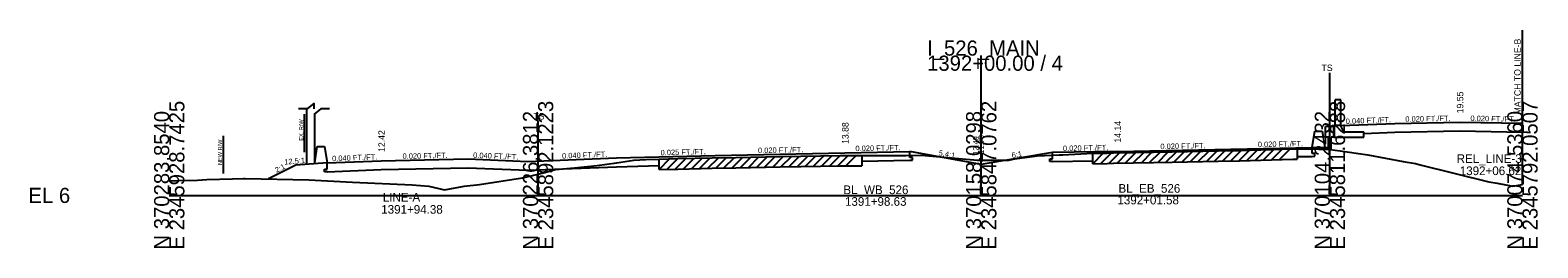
# Model space of a CAD drawing. Extents: x -170 to 2527928, y -10 to 1619750.
# Drawn here: x 1974.3 to 2252.8, y 4990.3 to 5030.5 of the extents above; entities that cross this region are included whole.
import ezdxf

# ---------------------------------------------------------------- set-up
doc = ezdxf.new("R2010")
doc.units = 0
for name, color, linetype in [('Default', 7, 'Continuous'), ('RD_GPK_XS_Cell', 7, 'Continuous'), ('RD_PD_NOISE-WALL-GM', 7, 'Continuous'), ('RD_PD_WallFill', 7, 'Continuous'), ('RD_XS_Base', 7, 'Continuous'), ('RD_XS_EarthShd', 7, 'Continuous'), ('RD_XS_ExGround', 7, 'Continuous'), ('RD_XS_ExPaveRet', 7, 'Continuous'), ('RD_XS_ExRW', 7, 'Continuous'), ('RD_XS_MatchLine', 7, 'Continuous'), ('RD_XS_NewRW', 7, 'Continuous'), ('RD_XS_Pave', 7, 'Continuous'), ('RD_XS_PaveShd', 7, 'Continuous'), ('RD_XS_TieSlope', 7, 'Continuous'), ('RD_XS_TX_Elev_EX', 7, 'Continuous'), ('RD_XS_TX_Elev_PR', 7, 'Continuous'), ('RD_XS_TX_Slope', 7, 'Continuous'), ('RD_XS_TX_Station', 7, 'Continuous')]:
    doc.layers.add(name, color=color, linetype=linetype)

msp = doc.modelspace()

# ---------------------------------------------------------------- linework, layer by layer
at = {"layer": 'Default'}
for p, q in [((2026.75, 5017.06), (2025.5, 5016.03)), ((2026.75, 5016.03), (2026.75, 5017.06)), ((2025.5, 5016.03), (2023.91, 5016.03)), ((2028, 5016.03), (2026.75, 5015.01)), ((2029.59, 5016.03), (2028, 5016.03))]:
    msp.add_line(p, q, dxfattribs=at)
at = {"layer": 'RD_GPK_XS_Cell'}
for p, q in [((2150.01, 5000), (2150.01, 5025.83)), ((2000, 5000), (2068.15, 5000)), ((2068.15, 5000), (2150.01, 5000)), ((2150.01, 5000), (2214.42, 5000)), ((2214.42, 5000), (2250, 5000))]:
    msp.add_line(p, q, dxfattribs=at)
at = {"layer": 'RD_PD_NOISE-WALL-GM'}
for p, q in [((2025.37, 5016.03), (2025.37, 5005.71)), ((2026.87, 5005.83), (2026.87, 5015.11)), ((2211.17, 5008.86), (2211.66, 5011.86)), ((2211.66, 5011.86), (2213, 5011.86)), ((2213, 5011.86), (2213.48, 5008.86)), ((2026.87, 5006.02), (2027.35, 5009.02)), ((2027.35, 5009.02), (2028.69, 5009.02)), ((2028.69, 5009.02), (2029.17, 5006.02))]:
    msp.add_line(p, q, dxfattribs=at)
at = {"layer": 'RD_PD_WallFill'}
for p, q in [((2215.42, 5012.91), (2215.42, 5017.66)), ((2216.42, 5017.66), (2215.42, 5017.66)), ((2216.42, 5012.91), (2216.42, 5017.66)), ((2215.14, 5012.74), (2213.64, 5012.74)), ((2213.64, 5010.74), (2213.64, 5012.74)), ((2215.3, 5012.91), (2215.13, 5012.74)), ((2215.14, 5010.74), (2215.14, 5012.74)), ((2215.21, 5012.74), (2215.14, 5012.74)), ((2215.21, 5012.82), (2215.21, 5010.74)), ((2216.42, 5012.91), (2215.3, 5012.91)), ((2216.42, 5012.91), (2216.42, 5012.74)), ((2216.42, 5012.74), (2216.92, 5011.74)), ((2216.92, 5011.74), (2220.71, 5011.74)), ((2220.71, 5010.74), (2220.71, 5011.74)), ((2214.14, 5010.74), (2213.64, 5010.74)), ((2214.14, 5008.51), (2214.14, 5010.74)), ((2215.14, 5010.74), (2214.64, 5010.74)), ((2214.64, 5008.47), (2214.64, 5010.74)), ((2215.14, 5010.74), (2220.71, 5010.74)), ((2215.21, 5010.74), (2215.14, 5010.74))]:
    msp.add_line(p, q, dxfattribs=at)
at = {"layer": 'RD_XS_Base'}
for p, q in [((2220.71, 5011.44), (2226.42, 5011.67)), ((2226.42, 5011.67), (2238.42, 5011.91)), ((2238.42, 5011.91), (2250, 5011.68)), ((2136.84, 5006.99), (2136.84, 5008.12)), ((2211.17, 5007.72), (2211.17, 5008.86)), ((2029.17, 5004.88), (2029.17, 5006.02)), ((2066.28, 5004.66), (2082.65, 5005.31)), ((2082.65, 5005.31), (2090.49, 5005.51)), ((2127.97, 5006.31), (2136.84, 5006.49)), ((2137.34, 5007), (2136.84, 5006.99)), ((2136.84, 5006.49), (2137.34, 5006.5)), ((2137.34, 5006.5), (2137.34, 5007)), ((2162.67, 5006.75), (2163.17, 5006.76)), ((2162.67, 5006.25), (2162.67, 5006.75)), ((2163.17, 5006.26), (2162.67, 5006.25)), ((2163.17, 5006.76), (2163.17, 5007.9)), ((2163.17, 5006.26), (2170.61, 5006.41)), ((2208.35, 5007.16), (2211.17, 5007.22)), ((2211.67, 5007.73), (2211.17, 5007.72)), ((2211.17, 5007.22), (2211.67, 5007.23)), ((2211.67, 5007.23), (2211.67, 5007.73)), ((2028.67, 5004.86), (2029.17, 5004.88)), ((2028.67, 5004.36), (2028.67, 5004.86)), ((2029.17, 5004.38), (2028.67, 5004.36)), ((2029.17, 5004.38), (2039.17, 5004.78)), ((2039.17, 5004.78), (2055.17, 5005.1)), ((2055.17, 5005.1), (2066.28, 5004.66))]:
    msp.add_line(p, q, dxfattribs=at)
at = {"layer": 'RD_XS_EarthShd'}
msp.add_line((2029.17, 5006.02), (2023.41, 5005.56), dxfattribs=at)
at = {"layer": 'RD_XS_ExGround'}
msp.add_lwpolyline([(2000, 5002.71), (2001.55, 5002.74), (2005.25, 5002.8), (2006.95, 5002.95), (2011.69, 5003.06), (2013.72, 5003.13), (2014.05, 5003.14), (2025.81, 5002.87), (2033.84, 5002.42), (2044.87, 5001.98), (2047.94, 5001.68), (2050.87, 5001), (2054.48, 5001.71), (2057.29, 5002.03), (2065.26, 5003.23), (2068.15, 5003.94), (2069.37, 5004.24), (2071.31, 5004.76), (2074.85, 5005.08), (2079.05, 5005.5), (2082.66, 5006.05), (2085.85, 5006.5), (2088.05, 5006.61), (2090.49, 5006.72), (2093.99, 5006.8), (2100.3, 5006.94), (2104.66, 5007.03), (2112.89, 5007.17), (2116.67, 5007.24), (2123.93, 5007.37), (2125.3, 5007.38), (2127.97, 5007.37), (2136.11, 5007.39), (2138.97, 5007.43), (2149.31, 5006.51), (2149.47, 5006.49), (2149.49, 5006.49), (2149.53, 5006.49), (2149.68, 5006.49), (2150.01, 5006.49), (2155.09, 5006.53), (2156.2, 5006.73), (2160.37, 5007.32), (2164.38, 5007.49), (2165.09, 5007.52), (2170.61, 5007.78), (2173.29, 5007.83), (2174.46, 5007.86), (2181.81, 5008), (2185.29, 5008.06), (2193.8, 5008.24), (2197.74, 5008.32), (2207.57, 5008.59), (2208.35, 5008.61), (2208.68, 5008.6), (2210.2, 5008.58), (2214.46, 5008.5), (2216.32, 5008.24), (2221.43, 5007.5), (2227.95, 5006.26), (2230.22, 5005.89), (2231.1, 5005.64), (2243.81, 5002.51), (2245.34, 5002.25), (2248.24, 5001.68), (2250, 5002.02)], dxfattribs=at)
at = {"layer": 'RD_XS_ExPaveRet'}
for p, q in [((2184.11, 5006.12), (2186.06, 5008.08)), ((2185.61, 5006.15), (2187.57, 5008.11)), ((2187.11, 5006.18), (2189.07, 5008.14)), ((2188.61, 5006.22), (2190.57, 5008.17)), ((2190.11, 5006.25), (2192.07, 5008.2)), ((2191.61, 5006.28), (2193.57, 5008.24)), ((2193.11, 5006.31), (2195.07, 5008.27)), ((2194.61, 5006.34), (2196.56, 5008.3)), ((2196.11, 5006.37), (2198.07, 5008.33)), ((2197.61, 5006.4), (2199.58, 5008.37)), ((2199.11, 5006.44), (2201.08, 5008.41)), ((2200.61, 5006.48), (2202.58, 5008.45)), ((2202.11, 5006.52), (2204.08, 5008.49)), ((2203.61, 5006.56), (2205.58, 5008.54)), ((2205.11, 5006.61), (2207.08, 5008.58)), ((2208.35, 5008.61), (2208.35, 5006.69)), ((2090.49, 5004.8), (2092.45, 5006.76)), ((2090.49, 5004.8), (2090.49, 5006.72)), ((2091.99, 5004.83), (2093.95, 5006.8)), ((2093.49, 5004.87), (2095.46, 5006.83)), ((2094.99, 5004.9), (2096.96, 5006.87)), ((2096.49, 5004.94), (2098.46, 5006.9)), ((2097.99, 5004.97), (2099.96, 5006.94)), ((2099.49, 5005.01), (2101.45, 5006.97)), ((2100.99, 5005.04), (2102.95, 5006.99)), ((2102.49, 5005.07), (2104.45, 5007.02)), ((2103.99, 5005.1), (2105.95, 5007.05)), ((2105.49, 5005.12), (2107.45, 5007.08)), ((2106.99, 5005.15), (2108.95, 5007.1)), ((2108.49, 5005.18), (2110.45, 5007.13)), ((2109.99, 5005.2), (2111.95, 5007.16)), ((2111.49, 5005.23), (2113.45, 5007.18)), ((2112.89, 5005.26), (2116.67, 5005.33)), ((2112.99, 5005.26), (2114.95, 5007.21)), ((2114.49, 5005.29), (2116.45, 5007.24)), ((2115.99, 5005.31), (2117.95, 5007.27)), ((2116.67, 5005.33), (2123.93, 5005.46)), ((2117.49, 5005.34), (2119.45, 5007.29)), ((2118.99, 5005.37), (2120.95, 5007.32)), ((2120.49, 5005.4), (2122.45, 5007.35)), ((2121.99, 5005.42), (2123.95, 5007.37)), ((2123.49, 5005.45), (2125.42, 5007.38)), ((2123.93, 5005.46), (2125.3, 5005.46)), ((2124.99, 5005.46), (2126.91, 5007.37)), ((2125.3, 5005.46), (2127.97, 5005.46)), ((2127.97, 5007.37), (2127.97, 5005.46)), ((2170.61, 5005.86), (2172.56, 5007.82)), ((2170.61, 5005.86), (2170.61, 5007.78)), ((2170.61, 5005.86), (2173.29, 5005.92)), ((2172.11, 5005.89), (2174.07, 5007.85)), ((2173.29, 5005.92), (2174.46, 5005.94)), ((2173.61, 5005.92), (2175.56, 5007.88)), ((2174.46, 5005.94), (2181.81, 5006.08)), ((2175.11, 5005.95), (2177.06, 5007.91)), ((2176.61, 5005.98), (2178.56, 5007.93)), ((2178.11, 5006.01), (2180.06, 5007.96)), ((2179.61, 5006.04), (2181.56, 5007.99)), ((2181.11, 5006.07), (2183.06, 5008.02)), ((2181.81, 5006.08), (2185.29, 5006.15)), ((2182.61, 5006.09), (2184.56, 5008.05)), ((2185.29, 5006.15), (2193.8, 5006.32)), ((2193.8, 5006.32), (2197.74, 5006.4)), ((2197.74, 5006.4), (2207.57, 5006.67)), ((2207.57, 5006.67), (2208.35, 5006.69)), ((2090.49, 5004.8), (2093.99, 5004.88)), ((2093.99, 5004.88), (2100.3, 5005.03)), ((2100.3, 5005.03), (2104.66, 5005.11)), ((2104.66, 5005.11), (2112.89, 5005.26))]:
    msp.add_line(p, q, dxfattribs=at)
at = {"layer": 'RD_XS_ExRW'}
msp.add_line((2025, 5008.01), (2025, 5015.01), dxfattribs=at)
at = {"layer": 'RD_XS_MatchLine'}
for p, q in [((2250, 5002.02), (2250, 5030.54)), ((2214.42, 5000), (2214.42, 5022.66)), ((2068.15, 5000), (2068.15, 5013.78))]:
    msp.add_line(p, q, dxfattribs=at)
at = {"layer": 'RD_XS_NewRW'}
msp.add_line((2010, 5004.02), (2010, 5011.02), dxfattribs=at)
at = {"layer": 'RD_XS_Pave'}
for p, q in [((2226.42, 5013.31), (2238.42, 5013.55)), ((2238.42, 5013.55), (2250, 5013.32)), ((2175.17, 5008.14), (2199.17, 5008.62)), ((2039.17, 5006.42), (2055.17, 5006.74)), ((2082.65, 5006.95), (2100.84, 5007.4)), ((2100.84, 5007.4), (2124.84, 5007.88))]:
    msp.add_line(p, q, dxfattribs=at)
at = {"layer": 'RD_XS_PaveShd'}
for p, q in [((2216.42, 5012.91), (2226.42, 5013.31)), ((2124.84, 5007.88), (2136.84, 5008.12)), ((2175.17, 5008.14), (2163.17, 5007.9)), ((2199.17, 5008.62), (2211.17, 5008.86)), ((2211.17, 5008.86), (2214.14, 5008.86)), ((2029.17, 5006.02), (2039.17, 5006.42)), ((2055.17, 5006.74), (2066.28, 5006.29)), ((2066.28, 5006.29), (2082.65, 5006.95))]:
    msp.add_line(p, q, dxfattribs=at)
at = {"layer": 'RD_XS_TieSlope'}
for p, q in [((2150.01, 5005.7), (2136.84, 5008.12)), ((2023.41, 5005.56), (2018.37, 5003.04)), ((2163.17, 5007.9), (2150.01, 5005.7))]:
    msp.add_line(p, q, dxfattribs=at)

# ---------------------------------------------------------------- texts
at = {"layer": 'RD_GPK_XS_Cell'}
for s, p in [('I_526_MAIN', (2140.01, 5025.83)), ('1392+00.00 / 4', (2140.01, 5023.03)), ('EL 6', (1974, 4998.6))]:
    msp.add_text(s, height=2.8, dxfattribs=at).set_placement(p)
for s, p in [('E 2345928.7425', (2002.8, 4990)), ('E 2345892.1223', (2070.95, 4990)), ('E 2345847.0762', (2152.81, 4990)), ('E 2345811.6288', (2217.22, 4990)), ('E 2345792.0507', (2252.8, 4990)), ('N 370283.8540', (2000, 4990)), ('N 370226.3812', (2068.15, 4990)), ('N 370158.0298', (2150.01, 4990)), ('N 370104.2432', (2214.42, 4990)), ('N 370074.5360', (2250, 4990))]:
    msp.add_text(s, height=2.8, rotation=90, dxfattribs=at).set_placement(p)
at = {"layer": 'RD_XS_ExRW'}
msp.add_text('EX. R/W ', height=0.75, rotation=90, dxfattribs=at).set_placement((2024.75, 5010.09))
at = {"layer": 'RD_XS_MatchLine'}
msp.add_text('MATCH TO LINE-B', height=1.2, rotation=90, dxfattribs=at).set_placement((2249.68, 5014.97))
for p in [(2212.88, 5022.98), (2067.29, 5014.03)]:
    msp.add_text('TS', height=1.2, dxfattribs=at).set_placement(p)
at = {"layer": 'RD_XS_NewRW'}
msp.add_text('NEW R/W ', height=0.75, rotation=90, dxfattribs=at).set_placement((2009.75, 5005.61))
at = {"layer": 'RD_XS_TX_Elev_EX'}
msp.add_text('12.49', height=1, rotation=90, dxfattribs=at).set_placement((2149.51, 5007.49))
at = {"layer": 'RD_XS_TX_Elev_PR'}
msp.add_text('11.70', height=1, rotation=90, dxfattribs=at).set_placement((2150.51, 5007.7))
at = {"layer": 'RD_XS_TX_Slope'}
for s, rotation, p in [('0.040 FT./FT.', 2.2906, (2217.37, 5013.19)), ('0.020 FT./FT.', 1.1458, (2228.37, 5013.6)), ('0.020 FT./FT.', 358.8542, (2240.38, 5013.76)), ('0.040 FT./FT.', 2.2906, (2072.59, 5006.8)), ('0.025 FT./FT.', 1.4321, (2090.78, 5007.4)), ('0.020 FT./FT.', 1.1458, (2108.78, 5007.81)), ('0.020 FT./FT.', 1.1458, (2126.78, 5008.17)), ('5.4:1', 349.5782, (2142.09, 5007.41)), ('6:1', 9.4623, (2155.72, 5006.91)), ('0.020 FT./FT.', 1.1458, (2165.12, 5008.19)), ('0.020 FT./FT.', 1.1458, (2183.12, 5008.55)), ('0.020 FT./FT.', 1.1458, (2201.12, 5008.91)), ('2:1', 26.5651, (2019.83, 5004.15)), ('12.5:1', 4.5739, (2021.3, 5005.68)), ('0.040 FT./FT.', 2.2906, (2030.11, 5006.31)), ('0.020 FT./FT.', 1.1458, (2043.11, 5006.75)), ('0.040 FT./FT.', 357.7094, (2056.13, 5006.95))]:
    msp.add_text(s, height=1, rotation=rotation, dxfattribs=at).set_placement(p)
at = {"layer": 'RD_XS_TX_Station'}
for s, p in [(' 19.55', (2239.08, 5014.72)), (' 14.14', (2175.83, 5009.31)), (' 12.42', (2039.83, 5007.59)), (' 13.88', (2125.5, 5009.06))]:
    msp.add_text(s, height=1.2, rotation=90, dxfattribs=at).set_placement(p)
for s, p in [('REL_LINE-3', (2237.85, 5006)), ('1392+06.62', (2238.42, 5003.75)), ('LINE-A', (2039.46, 4998.87)), ('BL_WB_526', (2124.55, 5000.24)), ('1392+01.58', (2175.17, 4998.34)), ('BL_EB_526', (2175.37, 5000.49)), ('1391+94.38', (2039.17, 4996.62)), ('1391+98.63', (2124.84, 4998.08))]:
    msp.add_text(s, height=1.6, dxfattribs=at).set_placement(p)

doc.saveas('drawing.dxf')
